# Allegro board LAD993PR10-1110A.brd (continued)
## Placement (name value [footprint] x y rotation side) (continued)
PR1105  97.6K_0402_1%  [R_0402]  64.78 85.13 90 bottom
PR1106  10_0402_1%  [R_0402]  70.88 83.1 90 bottom
PR1107  0_0402_5%  [R0402_0OHM]  69.99 83.1 90 bottom
PR1108  49.9_0402_1%  [R_0402]  69.1 83.1 90 bottom
PR1109  100_0402_1%  [R_0402]  68.46 83.1 90 top
PR1110  27.4K_0402_1%  [R_0402]  65.73 85.03 270 top
PR1111  10.2K_0402_1%  [R_0402]  66.62 84.11 90 top
PR1112  1.91K_0402_1%  [R_0402]  68.21 83.1 90 bottom
PR1113  165K_0402_1%  [R_0402]  76.51 85.33 0 bottom
PR1114  16.9K_0402_1%  [R_0402]  76.72 84.14 270 bottom
PR1115  5.62K_0402_1%  [R_0402]  75.83 84.14 270 bottom
PR1116  110K_0402_1%  [R_0402]  74.94 84.14 270 bottom
PR1117  0_0402_5%  [R0402_0OHM]  67.57 83.1 90 top
PR1118  3.6K_0402_1%  [R_0402]  65.72 87.75 0 top
PR1119  2K_0402_1%  [R_0402]  65.72 88.76 0 bottom
PR1120  0_0402_5%  [R0402_0OHM]  67.32 83.1 90 bottom
PR1121  1.1K_0402_1%  [R_0402]  76.51 88 0 bottom
PR1122  1K_0402_1%  [R_0402]  66.56 86.91 90 bottom
PR1123  48.7K_0402_1%  [R_0402]  76.51 86.22 0 bottom
PR1124  1K_0402_1%  [R_0402]  78.37 87.1 90 bottom
PR1125  2.61K_0402_1%  [R_0402]  129.17 118.1 180 bottom
PR1126  11K_0402_1%  [R_0402]  79.44 86.35 0 bottom
PR1127  2.94K_0402_1%  [R_0402]  64.7 87.81 0 bottom
PR1128  1K_0402_1%  [R_0402]  80.72 91.1 90 bottom
PR1129  2.67K_0402_1%  [R_0402]  80.71 90.16 0 bottom
PR1130  2.61K_0402_1%  [R_0402]  86.88 121.35 270 bottom
PR1131  11K_0402_1%  [R_0402]  63.43 91.43 0 bottom
PR1132  1K_0402_1%  [R_0402]  65.73 90.49 270 top
PR1133  4.42K_0402_1%  [R_0402]  78.55 92.57 0 bottom
PR1134  2K_0402_1%  [R_0402]  76.77 90.67 0 bottom
PR1135  115K_0402_1%  [R_0402]  76.74 92.61 0 bottom
PR1136  432_0402_1%  [R_0402]  66.62 90.49 270 top
PR1137  374_0402_1%  [R_0402]  76.6 95.75 180 bottom
PR1138  11K_0402_1%  [R_0402]  74.81 96.69 90 bottom
PR1139  1K_0402_1%  [R_0402]  76.34 97.6 270 bottom
PR1140  2.61K_0402_1%  [R_0402]  118.88 114.49 270 bottom
PR1141  10.2K_0402_1%  [R_0402]  68.84 95.7 270 bottom
PR1142  1K_0402_1%  [R_0402]  70.62 96.94 90 top
PR1143  90.9K_0402_1%  [R_0402]  67.07 94.78 90 bottom
PR1144  27.4K_0402_1%  [R_0402]  68.84 96.69 90 bottom
PR1145  2K_0402_1%  [R_0402]  70.62 94.78 90 bottom
PR1146  2.43K_0402_1%  [R_0402]  70.61 95.62 0 top
PR1147  4.87K_0402_1%  [R_0402]  69.73 94.78 90 bottom
PR1400  1_0402_5%  [R_0402]  122.56 129.45 270 top
PR1401  0_0402_5%  [R0402_0OHM]  121.45 131.84 270 bottom
PR1402  1_0402_5%  [R_0402]  123.23 131.84 270 bottom
PR1403  10K_0402_1%  [R_0402]  120.98 129.73 270 bottom
PR1404  0_0402_5%  [R0402_0OHM]  122.34 131.84 270 bottom
PR1405  4.7_0603_1%  [R_0603]  126.5 132.26 270 bottom
PR1406  10_1206_5%  [R_1206]  124.79 121.28 0 top
PR1407  0_0402_5%  [R0402_0OHM-NPM]  123.77 120.14 270 bottom
PR1408  0_0402_5%  [R0402_0OHM-NPM]  123.77 115.93 90 bottom
PR1409  100K_0402_1%  [R_0402]  79.21 101.21 180 bottom
PR1410  3.65K_0603_1%  [R_0603]  79.7 102.35 180 bottom
PR1411  2.2_0402_1%  [R_0402]  75.65 102.1 180 bottom
PR1412  100K_0402_1%  [R_0402]  74.74 101.08 0 bottom
PR1413  100K_0402_1%  [R_0402]  75.65 100.07 180 bottom
PR1414  1_0402_5%  [R_0402]  110.88 129.73 270 top
PR1415  0_0402_5%  [R0402_0OHM]  111.01 132.02 270 bottom
PR1416  1_0402_5%  [R_0402]  112.79 132.02 270 bottom
PR1417  0_0402_5%  [R0402_0OHM]  111.9 132.02 270 bottom
PR1418  10K_0402_1%  [R_0402]  110.82 129.73 270 bottom
PR1419  4.7_0603_1%  [R_0603]  116.09 132.18 270 bottom
PR1420  10_1206_5%  [R_1206]  113.99 121.28 0 top
PR1421  0_0402_5%  [R0402_0OHM-NPM]  114.88 120.21 270 bottom
PR1422  0_0402_5%  [R0402_0OHM-NPM]  114.88 115.99 90 bottom
PR1423  100K_0402_1%  [R_0402]  77.23 103.06 270 bottom
PR1424  3.65K_0603_1%  [R_0603]  77.04 104.26 180 bottom
PR1425  2.2_0402_1%  [R_0402]  73.37 102.1 180 bottom
PR1426  100K_0402_1%  [R_0402]  73.37 101.08 180 bottom
PR1427  100K_0402_1%  [R_0402]  73.37 100.07 180 bottom
PR1428  1_0402_5%  [R_0402]  100.9 129.61 270 top
PR1429  0_0402_5%  [R0402_0OHM]  101.23 131.89 270 bottom
PR1430  1_0402_5%  [R_0402]  103.13 131.89 270 bottom
PR1431  0_0402_5%  [R0402_0OHM]  102.17 131.89 270 bottom
PR1432  10K_0402_1%  [R_0402]  100.91 129.61 270 bottom
PR1433  4.7_0603_1%  [R_0603]  106.44 132.13 270 bottom
PR1434  10_1206_5%  [R_1206]  104.09 121.15 0 top
PR1435  0_0402_5%  [R0402_0OHM-NPM]  105.23 119.98 270 bottom
PR1436  0_0402_5%  [R0402_0OHM-NPM]  105.23 115.89 90 bottom
PR1437  100K_0402_1%  [R_0402]  72.45 104.38 0 bottom
PR1438  3.65K_0603_1%  [R_0603]  74.11 106.04 0 bottom
PR1439  2.2_0402_1%  [R_0402]  70.95 102.1 180 bottom
PR1440  100K_0402_1%  [R_0402]  70.95 100.07 180 bottom
PR1441  100K_0402_1%  [R_0402]  70.95 101.08 180 bottom
PR1500  1_0402_5%  [R_0402]  90.69 129.61 270 top
PR1501  0_0402_5%  [R0402_0OHM]  91.07 131.89 270 bottom
PR1502  1_0402_5%  [R_0402]  92.85 131.89 270 bottom
PR1503  0_0402_5%  [R0402_0OHM]  91.96 131.89 270 bottom
PR1504  10K_0402_1%  [R_0402]  90.75 129.61 270 bottom
PR1505  4.7_0603_1%  [R_0603]  96.15 132.13 270 bottom
PR1506  0_0402_5%  [R0402_0OHM-NPM]  91.83 120.08 270 bottom
PR1507  0_0402_5%  [R0402_0OHM-NPM]  91.83 115.86 90 bottom
PR1508  4.7_1206_5%  [R_1206]  93.8 121.15 0 top
PR1509  3.65K_0603_1%  [R_0603]  65.35 102.23 180 bottom
PR1510  100K_0402_1%  [R_0402]  64.86 101.08 180 bottom
PR1511  2.2_0402_1%  [R_0402]  65.87 103.37 180 bottom
PR1512  1_0402_5%  [R_0402]  71.51 106.97 90 bottom
PR1513  0_0402_5%  [R0402_0OHM]  67.37 108.58 0 bottom
PR1514  1_0402_5%  [R_0402]  67.37 110.35 0 bottom
PR1515  0_0402_5%  [R0402_0OHM]  67.37 109.46 0 bottom
PR1516  10K_0402_1%  [R_0402]  70.62 106.97 90 bottom
PR1517  4.7_0603_1%  [R_0603]  67.13 113.66 0 bottom
PR1518  4.7_1206_5%  [R_1206]  76.93 115.79 0 top
PR1519  0_0402_5%  [R0402_0OHM-NPM]  80.07 116.96 0 bottom
PR1520  0_0402_5%  [R0402_0OHM-NPM]  84.29 116.96 180 bottom
PR1521  3.65K_0603_1%  [R_0603]  66.49 106.54 180 bottom
PR1522  100K_0402_1%  [R_0402]  66.61 105.27 0 bottom
PR1523  2.2_0402_1%  [R_0402]  65.87 104.38 180 bottom
PR1524  4.7_1206_5%  [R_1206]  133.3 120.39 0 top
PR1525  100K_0402_1%  [R_0402]  65.87 103.37 180 top
PR1526  100K_0402_1%  [R_0402]  65.87 104.38 180 top
PR1527  1_0603_5%  [R_0603]  135.26 130.42 270 bottom
PR1528  3.65K_0603_1%  [R_0603]  132.79 117.21 180 top
PR1529  0_0402_5%  [R0402_0OHM]  132.55 116.07 180 top
PR1530  0_0402_5%  [R0402_0OHM]  131.84 130.17 270 bottom
PR1531  1_0402_5%  [R_0402]  132.85 130.17 270 top
PR1532  0_0402_5%  [R0402_0OHM]  130.69 127.37 90 bottom
PR1533  1_0402_5%  [R_0402]  130.82 127.83 270 top
PR1600  10K_0402_1%  [R_0402]  177.45 59.4 270 bottom
PR1601  0_0402_5%  [R0402_0OHM]  178.83 58.18 0 top
PR1602  169K_0402_1%  [R_0402]  176.51 58.49 90 bottom
PR1603  0_0402_5%  [R0402_0OHM]  178.78 59.43 270 bottom
PR1606  20.5K_0402_1%  [R_0402]  178.83 55.51 0 top
PR1607  4.32K_0402_1%  [R_0402]  178.83 56.41 0 bottom
PR1608  6.19K_0402_1%  [R_0402]  179.74 56.38 180 top
PR1609  16.5K_0402_1%  [R_0402]  178.82 57.37 0 bottom
PR1610  2.2_0603_5%  [R_0603]  173.5 57.96 90 bottom
PR1611  10_1206_5%  [R_1206]  162.95 60.37 270 top
PR1612  309_0402_1%  [R_0402]  181.11 57.39 270 bottom
PR1613  2.2_0603_5%  [R_0603]  172.73 54.96 180 bottom
PR1614  20_0402_1%  [R_0402]  178.85 53.33 0 top
PR1615  453K_0402_1%  [R_0402]  179.77 53.33 180 bottom
PR1616  2.2_0603_5%  [R_0603]  173.48 51.93 270 bottom
PR1617  100_0402_1%  [R_0402]  179.77 52.44 180 top
PR1618  0_0402_5%  [R0402_0OHM]  179.77 52.45 180 bottom
PR1619  0_0402_5%  [R0402_0OHM]  175.55 51.76 270 bottom
PR1620  0_0402_5%  [R0402_0OHM]  179.59 50.47 180 bottom
PR1621  100K_0402_1%  [R_0402]  176.57 51.78 270 top
PR1622  10_1206_5%  [R_1206]  146.72 58.16 180 top
PR1623  100_0402_1%  [R_0402]  177.66 50.84 90 bottom
PR1624  10K_0402_5%  [R_0402]  175.55 51.73 270 top
PR1700  10K_0402_1%  [R_0402]  200.77 51.58 0 top
PR1701  0_0402_5%  [R_0402]  201.68 50.66 180 top
PR1702  0_0402_5%  [R0402_0OHM]  201.68 52.47 180 top
PR1703  0_0402_5%  [R0402_0OHM]  200.79 49.72 0 top
PR1706  20.5K_0402_1%  [R_0402]  204.35 48.94 270 bottom
PR1707  4.32K_0402_1%  [R_0402]  203.46 48.86 270 top
PR1708  6.19K_0402_1%  [R_0402]  203.46 48.02 90 bottom
PR1709  16.5K_0402_1%  [R_0402]  202.57 48.86 270 top
PR1710  10_1206_5%  [R_1206]  193.39 66.84 90 top
PR1711  2.2_0603_5%  [R_0603]  202.32 56.01 90 top
PR1712  309_0402_1%  [R_0402]  201.69 47.95 90 top
PR1713  2.2_0603_5%  [R_0603]  206.59 55.98 90 top
PR1714  20_0402_1%  [R_0402]  208.42 48.94 270 top
PR1715  412K_0402_1%  [R_0402]  207.53 48.02 90 top
PR1716  100_0402_1%  [R_0402]  210.19 48.25 180 top
PR1717  0_0402_5%  [R0402_0OHM]  210.19 49.16 180 top
PR1719  82.5K_0402_1%  [R_0402]  208.42 53.86 0 top
PR1720  0_0402_5%  [R0402_0OHM]  210.19 50.05 90 top
PR1721  100_0402_1%  [R_0402]  209.31 51.88 270 top
PR1800  100K_0402_1%  [R_0402]  150.78 20.6 180 bottom
PR1801  0_0402_5%  [R0402_0OHM]  147.15 16.31 180 bottom
PR1803  21.5K_0402_1%  [R_0402]  146.14 26.74 0 bottom
PR1804  10K_0402_1%  [R_0402]  148.16 26.75 270 bottom
PR1805  0_0603_1%  [R_0603]  144.1 26.88 180 top
PT1400  PAD~D  [TPC12]  121.04 125.09 90 bottom
PT1401  PAD~D  [TPC12]  110.88 125.09 90 bottom
PT1402  PAD~D  [TPC12]  100.97 125.09 90 bottom
PT1500  PAD~D  [TPC12]  89.67 125.09 90 bottom
PT1501  PAD~D  [TPC12]  74.86 107.53 180 bottom
PT1503  PAD~D  [TPC12]  130.72 124.41 180 bottom
PU300  BQ24780SRUYR_QFN28_4X4  [BQ24780RUYR_WQFN28_4X4-S]  27.82 36.14 0 bottom
PU400  -  [TPS51285BRUKR_QFN20_3X3]  53.82 22.36 180 bottom
PU500  SY8210AQVC_QFN19_4X3  [SY8210AQVC_QFN19_4X3-S]  99.35 12.91 0 bottom
PU600  -  [SY8286RAC_QFN20_3X3]  249.55 17.16 270 bottom
PU700  -  [SY8286RAC_QFN20_3X3]  68.4 69.04 270 top
PU800  -  [SY8286RAC_QFN20_3X3]  222.26 45.2 270 bottom
PU900  APW8828QBI-TRG_TDFN10_3X3  [TPS51212DSCR_SON10_3X3-S]  141.81 111.56 180 bottom
PU1000  -  [SY8286RAC_QFN20_3X3]  206.12 119.95 270 bottom
PU1100  ISL95829AHRTZ-T_TQFN48_6X6  [ISL95855HRTZTS27_TQFN48_6X6-S]  68.72 87.37 0 bottom
PU1400  -  [SIC632CDT1GE3_POWERPAK31_5X5]  123.16 129.18 270 bottom
PU1401  -  [SIC632CDT1GE3_POWERPAK31_5X5]  113 129.18 270 bottom
PU1402  -  [SIC632CDT1GE3_POWERPAK31_5X5]  103.1 129.05 270 bottom
PU1500  -  [SIC632CDT1GE3_POWERPAK31_5X5]  92.81 129.05 270 bottom
PU1501  -  [SIC632CDT1GE3_POWERPAK31_5X5]  70.11 110.32 0 bottom
PU1503  SIC531CDT1GE3_POWERPAK22_4X3  [SIC531CDT1GE3_POWERPAK22_4X3-S]  132.85 127.24 270 bottom
PU1600  -  [RT8816AGQW_WQFN20_3X3]  174.84 56.48 0 bottom
PU1700  -  [RT8816AGQW_WQFN20_3X3]  203.64 53.76 270 top
PU1800  -  [RT9059GSP_SO8]  147.5 18.98 180 bottom
Q12  L2N7002LT1G_SOT23-3  [2N7002K_SOT23-3]  58.94 31.11 180 top
Q13  L2N7002LT1G_SOT23-3  [2N7002K_SOT23-3]  244.36 32.02 180 top
QA1  -  [L2N7002WT1G_SC-70-3]  264.55 27.36 0 bottom
QA2  SI3457BDV-T1-E3_TSOP6~D  [SI3457BDV-T1-E3_TSOP6]  261.06 30.58 270 bottom
QE3  -  [L2N7002WT1G_SC-70-3]  213.44 32.5 90 top
QE4  -  [DMG2301U-7_SOT23-3]  210.83 34.31 180 top
QE5  -  [L2N7002WT1G_SC-70-3]  118.56 15.71 270 top
QE13  -  [L2N7002WT1G_SC-70-3]  133.1 15.9 0 top
QE19  2N7002EDW 2N SOT-363-6  [DMN65D8LDW-7_SOT363-6]  148.78 16.35 90 bottom
QE20  2N7002EDW 2N SOT-363-6  [DMN65D8LDW-7_SOT363-6]  253.12 28.95 180 top
QE21  2N7002EDW 2N SOT-363-6  [DMN65D8LDW-7_SOT363-6]  256.55 27.17 90 top
QE23  2N7002EDW 2N SOT-363-6  [DMN65D8LDW-7_SOT363-6]  247.15 27.04 0 top
QE24  2N7002EDW 2N SOT-363-6  [DMN65D8LDW-7_SOT363-6]  285.62 58.98 0 bottom
QH4  2N7002EDW 2N SOT-363-6  [DMN65D8LDW-7_SOT363-6]  152.47 21.37 90 top
QH5  2N7002EDW 2N SOT-363-6  [DMN65D8LDW-7_SOT363-6]  151.92 23.81 180 bottom
QT1  MMBT3904WH_SOT323-3  [MMST3904-7-F_SOT323-3]  150.18 75.56 90 top
QT2  2N7002EDW 2N SOT-363-6  [DMN65D8LDW-7_SOT363-6]  52.4 47.35 90 bottom
QT3  MMBT3904WH_SOT323-3  [MMST3904-7-F_SOT323-3]  215.43 14.83 270 bottom
QV1  DMN63D8LDW-7 2N SOT363-6  [DMN65D8LDW-7_SOT363-6]  149.17 73.46 270 bottom
QV2  -  [L2N7002WT1G_SC-70-3]  66.81 23.93 180 top
QV3  BSS138W 1N SOT-323-3  [2N7002W-T-R7_SOT323-3]  147.71 77.85 0 top
QV10  BSS138W 1N SOT-323-3  [2N7002W-T-R7_SOT323-3]  177.26 63.08 0 top
QV11  SI3457BDV-T1-E3_TSOP6~D  [SI3457BDV-T1-E3_TSOP6]  62.38 21 0 top
QV20  BSS138W 1N SOT-323-3  [2N7002W-T-R7_SOT323-3]  191.02 119.15 0 bottom
QV21  BSS138W 1N SOT-323-3  [2N7002W-T-R7_SOT323-3]  194.74 74.41 270 bottom
QV88  DMN63D8LDW-7 2N SOT363-6  [DMN65D8LDW-7_SOT363-6]  151.09 76.65 180 bottom
QV89  -  [L2N7002WT1G_SC-70-3]  172.73 69.71 0 top
QV90  DMN61D9UDW-7 2N SOT363-6  [DMN65D8LDW-7_SOT363-6]  190.96 61.47 270 top
QV92  DMN63D8LDW-7 2N SOT363-6  [DMN65D8LDW-7_SOT363-6]  207.37 60.1 90 top
QV93  S TR METR3904W-G NPN SOT323-3  [MMST3904-7-F_SOT323-3]  228.8 17.55 90 bottom
QZ6  DMN63D8LDW-7 2N SOT363-6  [DMN65D8LDW-7_SOT363-6]  204.35 70.6 0 top
QZ7  DMN63D8LDW-7 2N SOT363-6  [DMN65D8LDW-7_SOT363-6]  157.5 77.55 90 top
QZ8  DMN63D8LDW-7 2N SOT363-6  [DMN65D8LDW-7_SOT363-6]  150.09 107.03 270 top
QZ9  -  [DMG2301U-7_SOT23-3]  210.98 47.79 270 bottom
QZ10  DMN63D8LDW-7 2N SOT363-6  [DMN65D8LDW-7_SOT363-6]  155.49 79.97 0 top
QZ11  -  [L2N7002WT1G_SC-70-3]  150.62 80.06 0 top
QZ12  DMN63D8LDW-7 2N SOT363-6  [DMN65D8LDW-7_SOT363-6]  153.81 80.06 180 top
QZ13  DMN63D8LDW-7 2N SOT363-6  [DMN65D8LDW-7_SOT363-6]  30.47 39.26 0 top
R1  1M_0402_5%  [R_0402]  30.26 35.68 90 top
R2  4.7K_0805_5%  [R_0805]  28.74 41.07 270 top
R3  1M_0402_5%  [R_0402]  28.88 42.1 0 top
R4  1M_0402_5%  [R_0402]  30.63 42.1 0 top
R5  1M_0402_5%  [R_0402]  32.01 37.71 180 top
RA1  0_0402_5%  [R0402_0OHM]  286.2 30.23 270 bottom
RA2  10K_0402_5%  [R_0402]  289.32 39.16 90 top
RA3  0_0603_5%  [R0603_0OHM]  288.49 30.22 90 top
RA5  0_0402_5%  [R0402_0OHM]  274.13 18.41 0 top
RA7  0_0805_5%  [R0805_0OHM]  273.38 32.78 270 bottom
RA8  0_0603_5%  [R0603_0OHM]  290.73 22.99 45 top
RA9  0_0402_5%  [R0402_0OHM]  279.01 21.79 135 bottom
RA10  0_0805_5%  [R0805_0OHM]  275.09 32.78 270 bottom
RA11  100K_0402_5%  [R_0402]  287.87 21.33 180 top
RA12  0_0402_5%  [R0402_0OHM]  291.47 14.29 270 bottom
RA13  0_0402_5%  [R0402_0OHM]  292.16 22.22 0 top
RA14  0_0402_5%  [R0402_0OHM]  284.19 23.8 180 bottom
RA15  0_0402_5%  [R0402_0OHM]  294.98 11.8 180 top
RA16  0_0805_5%  [R0805_0OHM]  279.05 17.68 270 bottom
RA17  0_0402_5%  [R_0402]  281.44 18.74 270 top
RA18  0_0402_5%  [R0402_0OHM]  282.33 18.74 270 top
RA19  0_0402_5%  [R0402_0OHM]  279.41 20.13 270 top
RA22  200K_0402_5%  [R_0402]  278.46 19.18 270 top
RA23  100K_0402_5%  [R_0402]  275.6 30.6 270 top
RA24  100K_0402_5%  [R_0402]  275.9 18.41 0 top
RA27  0_0402_5%  [R0402_0OHM]  272.22 27.23 0 top
RA28  22_0402_5%  [R_0402]  272.22 26.34 0 top
RA29  0_0402_5%  [R0402_0OHM]  274.63 25.9 0 bottom
RA30  1K_0402_5%  [R_0402]  279.61 15.66 90 top
RA31  0_0402_5%  [R0402_0OHM]  276.36 23.92 0 bottom
RA32  33_0402_5%  [R_0402]  274.51 23.74 0 top
RA33  10K_0402_5%  [R_0402]  280.5 16.58 270 top
RA35  4.7_0402_5%  [R_0402]  273.62 23.99 0 bottom
RA36  10_0201_5%  [R_0201]  270.46 23.83 90 top
RA37  10_0201_5%  [R_0201]  273.25 23.95 90 top
RA42  2.2K_0402_5%  [R_0402]  287.49 20.06 180 bottom
RA43  2.2K_0402_5%  [R_0402]  288.99 20.06 0 bottom
RA44  10_0402_1%  [R_0402]  296.48 13.2 0 top
RA46  4.7K_0402_5%  [R_0402]  296.48 12.31 0 top
RA48  1K_0402_5%  [R_0402]  296.48 14.09 0 top
RA49  10_0402_1%  [R_0402]  292.57 15.36 180 top
RA51  1K_0402_5%  [R_0402]  292.57 14.47 180 top
RA53  4.7K_0402_5%  [R_0402]  292.57 16.25 180 top
RA54  10K_0402_5%  [R_0402]  292.57 18.02 180 top
RA55  10K_0402_5%  [R_0402]  296.48 15.99 0 top
RA56  0_0402_5%  [R0402_0OHM]  291.6 15.79 90 bottom
RA57  10_0402_5%  [R_0402]  257.95 16.83 270 bottom
RA58  10_0402_5%  [R_0402]  269.12 16.68 90 bottom
RA60  0_0402_5%  [R_0402]  269.2 22.34 180 bottom
RA61  0_0402_5%  [R_0402]  269.2 23.49 180 bottom
RA62  10K_0402_5%  [R_0402]  268.28 21.45 0 bottom
RA63  10K_0402_5%  [R_0402]  266.33 23.94 270 bottom
RA64  10K_0402_5%  [R_0402]  268.28 24.37 0 bottom
RA65  45.3K_0402_1%  [R_0402]  261.88 23.94 270 bottom
RA66  0_0402_5%  [R_0402]  265.44 23.03 90 bottom
RA67  0_0402_5%  [R_0402]  262.77 23.03 90 bottom
RA70  100K_0402_5%  [R_0402]  276.49 26.96 90 bottom
RA71  1K_0402_1%  [R_0402]  284.62 17.44 90 top
RA72  1.2K_0201_1%  [R_0201]  283.73 18.35 270 top
RA73  665_0402_1%  [R_0402]  257.92 23.64 270 bottom
RA74  100K_0402_5%  [R_0402]  257.85 20.89 0 bottom
RA75  0_0805_5%  [R_0805]  270.52 20.4 270 bottom
RA76  0_0805_5%  [R0805_0OHM]  268.61 20.4 270 bottom
RA79  100K_0402_5%  [R_0402]  261.68 27.04 0 bottom
RA80  1M_0402_5%  [R_0402]  259.14 25.77 0 bottom
RC11  1K_0402_5%  [R_0402]  154.51 16.97 270 bottom
RD7  10K_0402_5%  [R_0402]  218.27 27.8 180 bottom
RD8  10K_0402_5%  [R_0402]  217.56 23.61 0 bottom
RD9  0_0402_5%  [R_0402]  218.15 21.2 180 bottom
RD10  10K_0402_5%  [R_0402]  205.11 19.88 270 bottom
RD31  0_0402_5%  [R0402_0OHM]  96.96 17.49 270 bottom
RD35  470_0402_1%  [R_0402]  97.85 17.49 270 bottom
RD58  0_0402_5%  [R0402_0OHM]  204.23 19.88 270 bottom
RD59  0_0402_5%  [R0402_0OHM]  217.43 26.79 0 bottom
RD62  0_0402_5%  [R_0402]  194.07 17.47 270 top
RE1  100K_0402_5%  [R_0402]  214.13 34.33 90 top
RE2  240_0402_1%  [R_0402]  209.86 36.19 0 top
RE3  47K_0402_5%  [R_0402]  120.65 16.55 270 top
RE4  100K_0402_1%  [R_0402]  119.76 16.55 270 top
RE7  2.4K_0402_5%  [R_0402]  149.81 15.08 270 bottom
RE9  2.4K_0402_5%  [R_0402]  149.87 19.69 0 bottom
RE10  10_0402_5%  [R_0402]  228.99 12.11 90 top
RE12  0_0603_5%  [R0603_0OHM]  240.4 20.37 180 top
RE13  27K_0402_1%~D  [R_0402]  230.58 28.74 90 bottom
RE14  100K_0402_1%  [R_0402]  229.69 28.74 90 bottom
RE15  0_0603_5%  [R0603_0OHM]  224.93 16.14 0 bottom
RE16  0_0603_5%  [R0603_0OHM]  221.94 34.66 0 bottom
RE17  43_0402_1%  [R_0402]  238.44 29.45 0 top
RE20  1K_0402_5%  [R_0402]  225.18 27.24 270 bottom
RE21  1K_0402_5%  [R_0402]  238.44 25.52 0 top
RE22  100K_0402_5%  [R_0402]  223.78 28.74 90 bottom
RE23  10K_0402_5%  [R_0402]  232.99 20.59 180 bottom
RE24  4.7K_0402_5%  [R_0402]  235.39 23.1 0 bottom
RE25  100K_0402_5%  [R_0402]  241.77 25.92 180 top
RE27  100K_0402_5%  [R_0402]  235.39 26.66 0 bottom
RE28  10K_0402_5%  [R_0402]  226.07 29.66 270 bottom
RE29  100K_0402_5%  [R_0402]  216.6 27.04 180 top
RE30  100K_0402_5%  [R_0402]  236.23 19.17 180 bottom
RE31  100K_0402_5%  [R_0402]  222.51 32.07 270 bottom
RE33  100K_0402_5%  [R_0402]  232.6 24.76 0 bottom
RE34  10K_0402_1%  [R_0402]  222.67 21.25 0 bottom
RE35  10K_0402_1%  [R_0402]  223.58 22.14 180 bottom
RE36  300_0402_5%  [R_0402]  232.61 27.5 270 bottom
RE38  100K_0402_5%  [R_0402]  232.6 23.87 0 bottom
RE39  100K_0402_5%  [R_0402]  217.76 29.33 180 top
RE40  15_0402_1%  [R_0402]  216.21 17.08 0 top
RE41  15_0402_1%  [R_0402]  216.21 19.8 0 top
RE42  15_0402_1%  [R_0402]  216.21 18.86 0 top
RE43  4.7K_0402_5%  [R_0402]  223.07 27.17 0 bottom
RE44  4.7K_0402_5%  [R_0402]  223.07 26.28 0 bottom
RE45  2.2K_0402_5%  [R_0402]  223.07 25.26 0 bottom
RE46  2.2K_0402_5%  [R_0402]  223.07 24.25 0 bottom
RE47  10K_0402_5%  [R_0402]  221.93 29.02 0 bottom
RE52  100K_0402_5%  [R_0402]  223.4 31.16 90 bottom
RE53  100K_0402_5%  [R_0402]  222.5 13.93 270 top
RE55  4.7K_0402_5%  [R_0402]  235.39 23.99 0 bottom
RE57  0_0402_5%  [R0402_0OHM]  238.44 27.55 0 top
RE58  0_0402_5%  [R0402_0OHM]  225.18 29.66 270 bottom
RE59  0_0402_5%  [R0402_0OHM]  216.21 20.69 0 top
RE60  49.9_0402_1%  [R_0402]  245.45 34.28 180 bottom
RE61  0_0402_5%  [R0402_0OHM]  221.61 13.93 270 top
RE62  0_0402_5%  [R0402_0OHM]  226.1 12.74 0 bottom
RE63  10K_0402_5%  [R_0402]  254.01 31.41 90 bottom
RE64  10K_0402_5%  [R_0402]  255.91 31.41 90 bottom
RE65  100K_0402_5%  [R_0402]  255.03 31.41 90 bottom
RE66  0_0402_5%  [R_0402]  223.61 34.53 180 top
RE67  0_0603_5%  [R0603_0OHM]  227.54 25.94 90 bottom
RE68  0_0402_5%  [R0402_0OHM]  240.85 26.81 0 top
RE71  15_0402_1%  [R_0402]  171.13 10.79 0 bottom
RE73  0_0402_5%  [R0402_0OHM]  233.56 25.82 90 bottom
RE81  100K_0402_5%  [R_0402]  52.08 31.94 270 top
RE82  10K_0402_5%  [R_0402]  55.76 29.59 180 top
RE83  100K_0402_5%  [R_0402]  51.19 31.94 270 top
RE84  10K_0402_5%  [R_0402]  243.57 36.95 0 top
RE87  100K_0402_5%  [R_0402]  134.82 14.91 270 top
RE93  0_0603_5%  [R0603_0OHM]  134.97 17.16 180 top
RE100  10K_0402_5%  [R_0402]  56.39 31.08 90 top
RE101  10K_0402_5%  [R_0402]  243.57 34.41 0 top
RE104  0_0603_5%  [R0603_0OHM]  55.25 30.55 90 top
RE105  0_0603_5%  [R0603_0OHM]  243.07 35.68 0 top
RE106  0_0402_5%  [R0402_0OHM]  220.79 34.53 0 top
RE108  10K_0402_5%  [R_0402]  216.21 17.97 0 top
RE109  0_0402_5%  [R0402_0OHM]  250.07 32.32 270 bottom
RE110  0_0402_5%  [R0402_0OHM]  251.09 32.32 270 bottom
RE111  0_0402_5%  [R0402_0OHM]  252.1 32.32 270 bottom
RE112  0_0402_5%  [R0402_0OHM]  253.12 32.32 270 bottom
RE113  100K_0402_5%  [R_0402]  230.51 34.46 90 top
RE114  100K_0402_5%  [R_0402]  239.35 28.44 180 top
RE116  0_0402_5%  [R0402_0OHM]  236.92 29.58 0 bottom
RE118  10K_0402_5%  [R_0402]  256.75 33.39 180 bottom
RE119  100K_0402_5%  [R_0402]  238.39 19.04 90 bottom
RE120  100K_0402_5%  [R_0402]  216.42 32.96 270 top
RE121  10K_0402_5%  [R_0402]  57.97 27.21 0 top
RE122  10K_0402_5%  [R_0402]  243.77 28.06 0 top
RE123  100K_0402_5%  [R_0402]  141.83 17.26 270 bottom
RE124  100K_0402_1%  [R_0402]  228.23 31.26 180 bottom
RE125  10K_0402_1%  [R_0402]  226.32 31.23 90 bottom
RE126  15_0402_1%  [R_0402]  171.26 8.37 0 bottom
RE127  15_0402_1%  [R_0402]  185.23 11.14 180 bottom
RE128  15_0402_1%  [R_0402]  171.26 7.36 0 bottom
RE129  15_0402_1%  [R_0402]  184.39 9.34 90 bottom
RH1  0_0402_5%  [R_0402]  168.79 14.54 270 bottom
RH9  0_0402_5%  [R0402_0OHM]  179.79 26.79 180 top
RH10  10K_0402_5%  [R_0402]  159.33 17.67 90 top
RH11  0_0402_5%  [R0402_0OHM]  173.8 14.21 0 bottom
RH13  100K_0402_5%  [R_0402]  178.52 25.9 180 top
RH14  5.1K_0402_1%  [R_0402]  153.86 25.52 0 top
RH15  5.1K_0402_1%  [R_0402]  153.86 24.63 0 top
RH16  22_0402_5%  [R_0402]  184.27 25.21 0 top
RH17  1K_0402_5%  [R_0402]  171.08 16.32 270 bottom
RH18  1K_0402_5%  [R_0402]  186.83 14.52 90 top
RH20  0_0402_5%  [R_0402]  160.81 35.72 0 top
RH21  1K_0402_5%  [R_0402]  149.5 20.36 90 top
RH22  1K_0402_5%  [R_0402]  154.52 22.72 180 top
RH23  1K_0402_5%  [R_0402]  158.71 24.29 180 top
RH24  24.9_0402_1%  [R_0402]  126.68 68.57 0 bottom
RH25  1K_0402_5%  [R_0402]  158.71 25.64 180 top
RH26  1K_0402_5%  [R_0402]  148.52 22.72 0 top
RH27  1K_0402_5%  [R_0402]  154.51 21.19 180 top
RH28  0_0402_5%  [R0402_0OHM]  105.78 105.23 180 bottom
RH29  100_0402_1%  [R_0402]  106.7 105.23 0 bottom
RH30  24.9_0402_1%  [R_0402]  127.14 99.99 90 top
RH31  0_0402_5%  [R0402_0OHM]  117.52 103.22 90 bottom
RH32  0_0402_5%  [R0402_0OHM]  105.78 104.27 180 bottom
RH33  100_0402_1%  [R_0402]  106.7 104.27 0 bottom
RH34  0_0402_5%  [R0402_0OHM]  114.26 82.16 270 top
RH38  0_0402_5%  [R0402_0OHM]  84.39 92.19 0 bottom
RH41  100_0402_1%  [R_0402]  116.63 103.22 90 bottom
RH45  2_0402_1%  [R_0402]  68.16 43.78 0 top
RH46  2_0402_1%  [R_0402]  111.39 20.51 270 top
RH47  0_0402_5%  [R0402_0OHM]  187.84 14.52 90 top
RH56  51_0402_5%  [R_0402]  84.9 95.88 0 top
RH57  49.9_0402_1%  [R_0402]  84.39 88.64 0 bottom
RH58  49.9_0402_1%  [R_0402]  84.39 90.41 0 bottom
RH59  49.9_0402_1%  [R_0402]  85.3 89.53 180 bottom
RH60  51_0402_5%  [R_0402]  82.1 95.49 0 bottom
RH61  51_0402_5%  [R_0402]  84.39 91.3 0 bottom
RH62  499_0402_1%  [R_0402]  150.81 27.17 0 bottom
RH63  499_0402_1%  [R_0402]  158 20.23 90 top
RH64  4.7K_0402_5%  [R_0402]  159.65 24.25 0 top
RH65  150K_0402_5%  [R_0402]  165.09 28.94 270 top
RH66  4.7K_0402_5%  [R_0402]  157.11 20.23 90 top
RH67  1M_0402_5%  [R_0402]  169.68 18.86 270 top
RH68  10K_0402_5%  [R_0402]  154.74 33.31 180 top
RH69  10K_0402_5%  [R_0402]  154.87 30.13 180 bottom
RH70  10M_0402_5%  [R_0402]  175.47 19.04 180 bottom
RH71  2.7K_0402_1%  [R_0402]  179.25 40.45 90 top
RH72  1M_0402_5%  [R_0402]  182 45.02 270 bottom
RH74  4.7K_0402_5%  [R_0402]  162.58 15.57 180 bottom
RH77  100K_0402_5%  [R_0402]  169.67 13.52 0 bottom
RH79  10K_0402_5%  [R_0402]  154.52 37.33 180 bottom
RH80  10K_0402_5%  [R_0402]  151.9 31.47 0 top
RH81  8.2K_0402_5%  [R_0402]  170.19 16.14 270 bottom
RH82  4.7K_0402_5%  [R_0402]  165.49 17.95 90 top
RH83  20K_0402_5%  [R_0402]  177.17 18.84 90 top
RH84  20K_0402_5%  [R_0402]  175.4 18.84 90 top
RH85  8.2K_0402_5%  [R_0402]  168.79 18.86 270 top
RH86  10K_0402_5%  [R_0402]  153.73 30.6 0 top
RH87  10K_0402_5%  [R_0402]  180.68 24.88 180 top
RH88  47K_0402_5%  [R_0402]  178.95 18.33 90 top
RH89  0_0402_5%  [R_0402]  154.74 35.21 180 top
RH90  10K_0402_5%  [R_0402]  171.46 18.86 270 bottom
RH91  10K_0402_5%  [R_0402]  153.98 27.93 0 bottom
RH92  4.7K_0402_5%  [R_0402]  164.6 18.46 90 top
RH93  220K_0402_5%  [R_0402]  80.49 81.83 0 bottom
RH94  10K_0402_5%  [R_0402]  187.78 25.07 180 top
RH95  51_0402_5%  [R_0402]  190.38 35.88 270 bottom
RH96  0_0402_5%  [R0402_0OHM]  182.97 19.04 180 bottom
RH97  51_0402_5%  [R_0402]  181.85 34.23 270 top
RH98  51_0402_5%  [R_0402]  183.65 31.56 270 top
RH100  51_0402_5%  [R_0402]  180.96 34.23 270 top
RH101  0_0402_5%  [R0402_0OHM]  161.67 14.63 0 bottom
RH102  0_0402_5%  [R_0402]  187.78 26.86 270 top
RH103  0_0402_5%  [R0402_0OHM]  192.08 23.78 180 top
RH104  22_0402_1%  [R_0402]  163.2 18.86 270 bottom
RH105  0_0402_5%  [R0402_0OHM]  191.16 24.67 0 top
RH106  0_0402_5%  [R0402_0OHM]  192.08 25.56 180 top
RH107  0_0402_5%  [R_0402]  116.37 81.24 0 top
RH108  100_0402_1%  [R_0402]  171 45.88 180 bottom
RH109  113_0402_1%  [R_0402]  179.08 29.86 0 top
RH110  10K_0402_5%  [R_0402]  154.74 32.42 180 top
RH111  10K_0402_5%  [R_0402]  180.68 23.99 180 top
RH112  1K_0402_5%  [R_0402]  175.21 32.46 90 top
RH113  1K_0402_5%  [R_0402]  182.13 34.97 90 bottom
RH114  0_0402_5%  [R0402_0OHM]  173.8 13.33 0 bottom
RH115  0_0402_5%  [R0402_0OHM]  84.9 94.1 0 top
RH118  0_0402_5%  [R0402_0OHM]  84.9 96.76 0 top
RH119  2.2K_0402_5%  [R_0402]  153.86 26.66 0 top
RH120  2.2K_0402_5%  [R_0402]  153.98 26.15 0 bottom
RH121  0_0603_5%  [R0603_0OHM]  171.84 12.25 90 bottom
RH122  0_0603_5%  [R0603_0OHM]  184.92 39.8 270 bottom
RH123  0_0603_5%  [R0603_0OHM]  180.35 28.82 180 top
RH124  0_0603_5%  [R0603_0OHM]  160.22 45.84 180 top
RH125  8.2K_0402_5%  [R_0402]  173.69 14.19 180 top
RH126  10K_0402_5%  [R_0402]  170.05 22.41 0 top
RH127  10K_0402_5%  [R_0402]  163.25 27.97 180 top
RH128  10K_0402_5%  [R_0402]  170.57 18.86 270 bottom
RH129  10K_0402_5%  [R_0402]  154.65 29.71 180 top
RH130  4.7K_0402_5%  [R_0402]  164.19 28.94 270 top
RH131  10K_0402_5%  [R_0402]  154.65 31.49 180 top
RH132  10K_0402_5%  [R_0402]  154.87 32.74 180 bottom
RH134  10K_0402_5%  [R_0402]  154.87 33.63 180 bottom
RH135  10K_0402_5%  [R_0402]  154.74 34.2 180 top
RH137  0_0603_5%  [R0603_0OHM]  166.62 15.64 0 top
RH138  13_0402_5%  [R_0402]  185.68 34.97 90 bottom
RH141  2.2K_0402_5%  [R_0402]  177.86 23.74 0 top
RH142  2.2K_0402_5%  [R_0402]  177.86 22.85 0 top
RH143  330K_0402_5%  [R_0402]  176.29 19.75 270 top
RH144  49.9_0402_1%  [R_0402]  84.9 94.99 0 top
RH145  20_0402_5%  [R_0402]  133.89 95.32 0 top
RH146  30_0402_5%  [R_0402]  188.35 35.88 270 bottom
RH147  30_0402_5%  [R_0402]  189.24 35.88 270 bottom
RH148  121_0402_1%  [R_0402]  124.65 68.57 0 bottom
RH149  75_0402_1%  [R_0402]  121.22 68.95 0 bottom
RH150  100_0402_1%  [R_0402]  123.33 68.62 90 bottom
RH151  100_0402_5%  [R_0402]  85.91 90.29 0 top
RH152  56.2_0402_1%  [R_0402]  84.97 90.21 90 top
RH153  220_0402_5%  [R_0402]  85.91 91.3 0 top
RH154  60.4_0402_1%  [R_0402]  130.74 76.41 90 top
RH155  20_0402_5%  [R_0402]  81.21 98.29 0 bottom
RH156  51_0402_5%  [R_0402]  82.1 93.46 0 bottom
RH158  499_0402_1%  [R_0402]  84.39 94.61 0 bottom
RH159  49.9K_0402_1%  [R_0402]  153.73 27.93 0 top
RH160  49.9K_0402_1%  [R_0402]  153.98 27.04 0 bottom
RH163  1K_0402_5%  [R_0402]  123.16 95.52 180 top
RH164  1K_0402_5%  [R_0402]  131.67 77.32 270 top
RH165  1K_0402_5%  [R_0402]  82.1 94.61 0 bottom
RH166  49.9_0402_1%  [R_0402]  84.39 93.34 0 bottom
RH167  30_0402_5%  [R_0402]  134.81 93.54 180 top
RH168  22_0402_5%  [R_0402]  170.57 18.86 270 top
RH179  10K_0402_5%  [R_0402]  167.01 18.86 270 top
RH180  100K_0402_5%  [R_0402]  189.39 23.78 0 top
RH181  10K_0402_5%  [R_0402]  172.09 16.32 270 bottom
RH183  1K_0402_5%  [R_0402]  89.16 90.87 270 top
RH184  1K_0402_5%  [R_0402]  88.27 90.87 270 top
RH185  1K_0402_5%  [R_0402]  85.3 85.91 180 bottom
RH186  1K_0402_5%  [R_0402]  85.3 84.95 180 bottom
RH187  1K_0402_5%  [R_0402]  85.3 86.86 180 bottom
RH188  1K_0402_5%  [R_0402]  85.3 87.75 180 bottom
RH189  30_0402_5%  [R_0402]  184.16 34.97 90 bottom
RH190  0_0402_5%  [R0402_0OHM]  81.21 99.43 0 bottom
RH191  620_0402_5%  [R_0402]  183.14 34.97 90 bottom
RH192  30_0402_5%  [R_0402]  134.81 94.43 180 top
RH193  8.2K_0402_5%  [R_0402]  182.05 20.06 0 bottom
RH196  0_0402_5%  [R_0402]  167.52 28.9 270 top
RH197  100_0402_1%  [R_0402]  107.62 106.3 180 bottom
RH198  0_0402_5%  [R0402_0OHM]  105.78 106.3 180 bottom
RH201  100_0402_1%  [R_0402]  119.43 103.22 90 bottom
RH202  0_0402_5%  [R0402_0OHM]  118.41 103.22 90 bottom
RH203  100_0402_1%  [R_0402]  107.62 102.81 180 bottom
RH204  0_0402_5%  [R0402_0OHM]  105.78 102.81 180 bottom
RH206  1K_0402_1%  [R_0402]  70.02 43.73 270 top
RH207  1K_0402_1%  [R_0402]  114.31 20.51 270 top
RH209  1K_0402_1%  [R_0402]  69.08 42.77 180 top
RH210  1K_0402_1%  [R_0402]  112.31 19.58 90 top
RH211  24.9_0402_1%  [R_0402]  70.02 44.72 90 top
RH212  24.9_0402_1%  [R_0402]  110.32 18.02 180 top
RH492  0_0402_5%  [R0402_0OHM]  184.54 30.65 90 top
RH493  0_0603_5%  [R0603_0OHM]  152.14 22.7 180 bottom
RH494  10K_0402_5%  [R_0402]  153.73 28.82 0 top
RH495  10K_0402_5%  [R_0402]  155.89 29.07 0 top
RH496  51_0402_5%  [R_0402]  83.07 91.48 90 bottom
RH497  51_0402_5%  [R_0402]  84.9 93.21 0 top
RH499  0_0402_5%  [R_0402]  190.31 22.9 180 top
RH500  10K_0402_5%  [R_0402]  167.9 18.86 270 top
RH502  0_0402_5%  [R0402_0OHM]  253.81 24.76 0 top
RH503  0_0402_5%  [R0402_0OHM]  180.35 18.33 90 top
RH504  100K_0402_5%  [R_0402]  250.58 27.17 90 top
RH505  100K_0402_5%  [R_0402]  249.56 27.17 90 top
RH506  100K_0402_5%  [R_0402]  284.11 58.36 270 bottom
RH507  22_0402_1%  [R_0402]  162.32 18.99 270 bottom
RH508  22_0402_1%  [R_0402]  164.09 18.86 270 bottom
RH509  22_0402_1%  [R_0402]  164.98 18.86 270 bottom
RH510  22_0402_1%  [R_0402]  165.87 18.86 270 bottom
RH513  0_0402_5%  [R0402_0OHM]  121.5 83.3 180 top
RH514  0_0402_5%  [R0402_0OHM]  121.5 84.19 180 top
RH515  100_0402_1%  [R_0402]  123.12 83.81 0 top
RH516  100_0402_1%  [R_0402]  123.12 82.92 0 top
RH517  100K_0402_5%  [R_0402]  176.74 61.37 0 top
RI9  100K_0402_5%  [R_0402]  277.94 34.66 0 top
RI10  100K_0402_5%  [R_0402]  277.94 35.68 0 top
RI30  100K_0402_5%  [R_0402]  277.89 37.71 0 top
RI37  0_0402_5%  [R0402_0OHM]  288.05 31.49 0 bottom
RI38  0_0402_5%  [R0402_0OHM]  288.05 32.5 0 bottom
RI39  0_0402_5%  [R0402_0OHM]  288.02 33.65 0 bottom
RI40  0_0402_5%  [R0402_0OHM]  288.02 34.66 0 bottom
RI41  0_0402_5%  [R0402_0OHM]  288.81 50.66 0 bottom
RI42  0_0402_5%  [R0402_0OHM]  288.81 51.68 0 bottom
RI43  0_0402_5%  [R0402_0OHM]  288.81 52.7 0 bottom
RI44  0_0402_5%  [R0402_0OHM]  288.81 53.71 0 bottom
RI45  22.1K_0402_1%  [R_0402]  285.05 36.92 0 top
RI49  22.1K_0402_1%  [R_0402]  285.05 36.03 0 top
RI51  1M_0402_5%  [R_0402]  277.89 36.69 0 top
RL1  0_0402_5%  [R_0402]  285.02 36.9 90 bottom
RL2  0_0402_5%  [R0402_0OHM]  286.14 39.79 90 bottom
RL19  75_0402_5%  [R_0402]  303.41 90.62 270 top
RL20  75_0402_5%  [R_0402]  300.36 90.62 270 top
RL27  100K_0402_5%  [R_0402]  279.49 53.2 270 bottom
RL30  15K_0402_1%  [R_0402]  285.91 37.81 270 bottom
RL31  2.49K_0402_1%  [R_0402]  280.82 47.48 0 bottom
RL33  1K_0402_5%  [R_0402]  287.93 37.81 180 bottom
RL39  75_0402_5%  [R_0402]  297.44 90.62 270 top
RL40  75_0402_5%  [R_0402]  294.52 90.62 270 top
RL41  100K_0402_5%  [R_0402]  277.45 48.25 180 bottom
RL42  1K_0402_5%  [R_0402]  285.63 41.6 270 top
RL43  0_0402_5%  [R0402_0OHM]  280.93 39.79 90 bottom
RM1  0_0402_5%  [R_0402]  272.17 29.84 270 top
RM2  0_0402_5%  [R_0402]  265.95 41.14 90 top
RM3  0_0402_5%  [R_0402]  265.06 41.14 90 top
RM22  0_0603_5%  [R0603_0OHM]  201.56 25.39 90 top
RM517  4.99K_0402_1%  [R_0402]  262.65 41.19 90 top
RM578  2K_0402_1%  [R_0402]  270.54 29.98 270 top
RM581  2K_0402_1%  [R_0402]  269.65 29.98 270 top
RM582  47K_0402_5%  [R_0402]  266.22 43.6 90 top
RM583  47K_0402_5%  [R_0402]  265.33 43.6 90 top
RM584  4.7K_0402_5%  [R_0402]  264.93 29.07 90 top
RM585  10K_0402_5%  [R_0402]  266.84 29.07 90 top
RM586  10K_0402_5%  [R_0402]  268.23 42.15 270 top
RM587  10K_0402_5%  [R_0402]  270.01 42.15 270 top
RM588  10K_0402_5%  [R_0402]  267.22 42.15 270 top
RM589  10K_0402_5%  [R_0402]  265.82 29.07 90 top
RM590  10K_0402_5%  [R_0402]  263.79 44.34 270 top
RM591  10K_0402_5%  [R_0402]  267.34 44.44 270 top
RM592  10K_0402_5%  [R_0402]  270.01 44.44 270 top
RM593  10K_0402_5%  [R_0402]  268.36 44.44 270 top
RM594  10K_0402_5%  [R_0402]  266.84 26.79 90 top
RM595  10K_0402_5%  [R_0402]  264.8 26.79 90 top
RM598  0_0603_5%  [R0603_0OHM]  263.53 40.38 270 bottom
RM599  0_0603_5%  [R0603_0OHM]  272.17 41.14 90 top
RM600  1K_0402_5%  [R_0402]  261.85 37.96 180 top
RN1  0_0402_5%  [R_0402]  195.15 35.09 90 bottom
RN2  0_0402_5%  [R_0402]  198.13 27.09 90 top
RN3  0_0402_5%  [R_0402]  195.16 28.69 0 top
RN4  100K_0402_5%  [R_0402]  195.16 29.58 0 top
RN5  0_0402_5%  [R0402_0OHM]  194.26 28.68 90 top
RP2  10K_0804_8P4R_5%  [RP_0804_8P4R]  169.42 17.45 90 bottom
RP3  10K_0804_8P4R_5%  [RP_0804_8P4R]  160.72 20.02 0 top
RP8  10K_0804_8P4R_5%  [RP_0804_8P4R]  154.38 36.24 180 bottom
RP15  33_0804_8P4R_5%  [RP_0804_8P4R]  181.62 15.74 90 bottom
RP22  10K_0804_8P4R_5%  [RP_0804_8P4R]  161.16 17.07 90 bottom
RP23  10K_0804_8P4R_5%  [RP_0804_8P4R]  158.24 17.07 90 bottom
RPE2  10K_0804_8P4R_5%  [RP_0804_8P4R]  233.19 34.85 90 top
RPE3  10K_0804_8P4R_5%  [RP_0804_8P4R]  229.77 32.32 270 bottom
RPE4  100K_0804_8P4R_5%  [RP_0804_8P4R]  215.5 25.45 0 top
RPE5  100K_0804_8P4R_5%  [RP_0804_8P4R]  224.43 11.48 90 top
RPE6  100K_0804_8P4R_5%  [RP_0804_8P4R]  235.27 20.32 0 bottom
RPE7  100K_0804_8P4R_5%  [RP_0804_8P4R]  239.98 22.61 180 top
RT1  7.87K_0402_1%  [R_0402]  109.31 83.94 180 top
RT3  10K_0402_5%  [R_0402]  57.08 46.47 0 bottom
RT4  10K_0402_5%  [R_0402]  55.38 47.79 90 bottom
RT5  10K_0402_5%  [R_0402]  51.32 48.2 270 bottom
RT6  0_0402_5%  [R_0402]  52.89 45.96 0 bottom
RT7  0_0402_5%  [R_0402]  53.81 49.77 180 bottom
RV27  100K_0402_5%  [R_0402]  173.64 73.55 180 bottom
RV34  10K_0402_5%  [R_0402]  150.31 74.86 270 bottom
RV37  10K_0402_5%  [R_0402]  171.46 74.67 180 top
RV39  10K_0402_5%  [R_0402]  148.07 80.44 0 bottom
RV40  0_0402_5%  [R0402_0OHM]  149.81 80.46 0 bottom
RV41  10K_0402_5%  [R_0402]  148.21 74.75 0 bottom
RV42  10K_0402_5%  [R_0402]  174.63 70.22 270 bottom
RV49  10K_0402_5%  [R_0402]  176.84 74.67 0 top
RV50  2.49K_0402_1%  [R_0402]  149.4 99.43 0 bottom
RV51  10K_0402_5%  [R_0402]  175.8 77.21 0 top
RV52  10M_0402_5%  [R_0402]  177.43 73.52 180 bottom
RV55  10K_0402_5%  [R_0402]  145.52 107.67 90 bottom
RV56  10K_0402_5%  [R_0402]  147.47 81.31 90 top
RV57  10K_0402_5%  [R_0402]  151.08 82.03 180 top
RV58  10K_0402_5%  [R_0402]  140.22 77.16 270 bottom
RV60  100K_0402_5%  [R_0402]  173.75 73.65 270 top
RV62  10K_0402_5%  [R_0402]  150.4 81.98 90 bottom
RV63  10K_0402_5%  [R_0402]  151.32 83.76 180 bottom
RV66  100K_0402_5%  [R_0402]  177.81 73.78 180 top
RV77  40.2_0402_1%  [R_0402]  174.56 97.53 0 top
RV78  40.2_0402_1%  [R_0402]  175.74 101.47 270 top
RV79  60.4_0402_1%  [R_0402]  180.9 96.61 180 top
RV95  10K_0402_5%  [R_0402]  173.49 127.45 270 top
RV96  10K_0402_5%  [R_0402]  205.7 89.53 180 top
RV98  10K_0402_5%  [R_0402]  168.67 127.09 270 top
RV99  10K_0402_5%  [R_0402]  205.57 95.46 180 top
RV107  10K_0402_5%  [R_0402]  168.7 125.35 270 top
RV108  10K_0402_5%  [R_0402]  173.49 125.54 270 top
RV110  10K_0402_5%  [R_0402]  203.82 95.49 180 top
RV111  10K_0402_5%  [R_0402]  203.92 89.48 180 top
RV116  1K_0402_1%  [R_0402]  171.71 131.56 90 top
RV117  1K_0402_1%  [R_0402]  169.8 129.45 270 top
RV120  121_0402_1%  [R_0402]  187.97 123.48 90 top
RV121  121_0402_1%  [R_0402]  154.31 123.99 90 top
RV125  549_0402_1%  [R_0402]  190.05 122.42 0 bottom
RV126  931_0402_1%  [R_0402]  190.76 120.56 90 bottom
RV127  1.33K_0402_1%  [R_0402]  188.28 124.98 90 bottom
RV131  1K_0402_1%  [R_0402]  206.26 93.51 90 top
RV132  1K_0402_1%  [R_0402]  205.17 91.18 0 top
RV135  121_0402_1%  [R_0402]  205.17 110.73 0 top
RV136  121_0402_1%  [R_0402]  201.86 75.17 0 top
RV140  549_0402_1%  [R_0402]  206.51 73.6 270 bottom
RV141  931_0402_1%  [R_0402]  201.86 73.14 0 bottom
RV142  1.33K_0402_1%  [R_0402]  203.8 74.67 0 bottom
RV146  100K_0402_5%  [R_0402]  183.52 74.03 270 top
RV147  100K_0402_5%  [R_0402]  191.39 74.36 270 top
RV148  100K_0402_5%  [R_0402]  190.51 74.41 270 top
RV149  100K_0402_5%  [R_0402]  186.69 74.36 270 top
RV150  100K_0402_5%  [R_0402]  184.53 74.36 270 top
RV152  100K_0402_5%  [R_0402]  179.94 74.93 180 top
RV153  100K_0402_5%  [R_0402]  191.02 76.32 270 top
RV154  100K_0402_5%  [R_0402]  190 76.32 270 top
RV155  100K_0402_5%  [R_0402]  186.69 76.65 270 top
RV156  100K_0402_5%  [R_0402]  184.53 76.65 270 top
RV157  100K_0402_5%  [R_0402]  187.58 74.36 270 top
RV158  100K_0402_5%  [R_0402]  189.62 74.41 270 top
RV159  100K_0402_5%  [R_0402]  185.42 74.36 270 top
RV160  100K_0402_5%  [R_0402]  187.58 76.65 270 top
RV161  100K_0402_5%  [R_0402]  188.73 75.81 90 top
RV162  100K_0402_5%  [R_0402]  185.42 76.65 270 top
RV191  1.8K_0402_5%  [R_0402]  161.38 73.52 180 bottom
RV192  1.8K_0402_5%  [R_0402]  164.35 73.6 270 bottom
RV199  0_0603_5%  [R_0603]  144.35 63.24 180 top
RV200  0_0603_5%  [R_0603]  144.35 61.97 180 top
RV208  0_0402_5%  [R0402_0OHM]  148.07 79.57 0 bottom
RV209  100K_0402_5%  [R_0402]  170.8 71.11 0 top
RV399  0_0402_5%  [R0402_0OHM]  152.3 76.32 0 top
RV512  1.8K_0402_5%  [R_0402]  170.87 81.24 0 top
RV513  1.8K_0402_5%  [R_0402]  170.88 77.46 0 top
RV514  1.8K_0402_5%  [R_0402]  165.24 73.6 270 bottom
RV515  1.8K_0402_5%  [R_0402]  168.02 73.7 270 bottom
RV526  10K_0402_5%  [R_0402]  170.7 73.52 270 bottom
RV532  10K_0402_5%  [R_0402]  147.56 76.19 0 bottom
RV534  100K_0402_5%  [R_0402]  151.43 76.44 270 top
RV535  1M_0402_5%  [R_0402]  66.89 21.83 180 top
RV536  100K_0402_5%  [R_0402]  62.8 29.96 0 top
RV537  100K_0402_5%  [R_0402]  62.8 30.98 0 top
RV538  0_0402_5%  [R0402_0OHM]  63.71 26.91 180 top
RV539  0_0402_5%  [R0402_0OHM]  55.24 37.25 0 bottom
RV540  0_0402_5%  [R0402_0OHM]  55.24 36.36 0 bottom
RV541  0_0402_5%  [R0402_0OHM]  55.24 39.03 0 bottom
RV542  0_0402_5%  [R0402_0OHM]  55.24 38.14 0 bottom
RV543  0_0402_5%  [R0402_0OHM]  55.24 40.8 0 bottom
RV544  0_0402_5%  [R0402_0OHM]  55.24 39.92 0 bottom
RV546  0_0402_5%  [R0402_0OHM]  55.24 42.71 0 bottom
RV548  0_0402_5%  [R0402_0OHM]  55.24 41.82 0 bottom
RV549  0_0402_5%  [R0402_0OHM]  55.24 34.58 0 bottom
RV551  100K_0402_5%  [R_0402]  62.8 31.87 0 top
RV552  0_0402_5%  [R0402_0OHM]  55.24 35.47 0 bottom
RV554  150_0402_5%  [R_0402]  293.81 65.27 0 top
RV557  150_0402_5%  [R_0402]  292.82 65.27 180 top
RV562  150_0402_5%  [R_0402]  296.89 75.94 180 top
RV565  150_0402_5%  [R_0402]  294.98 75.94 180 top
RV566  0_0402_5%  [R0402_0OHM]  63.71 28.95 180 top
RV567  100K_0402_5%  [R_0402]  62.77 25.95 0 top
RV570  100K_0402_5%  [R_0402]  65.97 22.72 0 top
RV571  0_0402_5%  [R_0402]  157.62 72.75 90 top
RV572  0_0402_5%  [R0402_0OHM]  145.22 73.4 0 bottom
RV573  100K_0402_5%  [R_0402]  156.73 72.75 90 top
RV574  10K_0402_5%  [R_0402]  173.75 77.51 270 top
RV575  10K_0402_5%  [R_0402]  169.81 73.65 270 bottom
RV576  10K_0402_5%  [R_0402]  168.92 73.65 270 bottom
RV577  10K_0402_5%  [R_0402]  171.99 79.77 270 top
RV578  10K_0402_5%  [R_0402]  167.14 73.7 270 bottom
RV579  10K_0402_5%  [R_0402]  171.83 73.57 270 bottom
RV580  10K_0402_5%  [R_0402]  170.1 76.56 0 top
RV581  10K_0402_5%  [R_0402]  188.48 74.29 270 top
RV582  100K_0402_5%  [R_0402]  175.42 62.86 270 top
RV583  0_0402_5%  [R0402_0OHM]  158 75.86 0 top
RV584  0_0402_5%  [R0402_0OHM]  163.55 81.5 0 top
RV585  0_0402_5%  [R0402_0OHM]  160.75 81.32 180 top
RV586  0_0402_5%  [R0402_0OHM]  163.89 80.66 270 top
RV587  0_0402_5%  [R_0402]  144.26 79.54 270 bottom
RV588  10K_0402_5%  [R_0402]  193.94 61.15 270 top
RV589  10K_0402_5%  [R_0402]  189.87 60.37 90 top
RV590  0_0402_5%  [R0402_0OHM]  155.88 82.79 180 top
RV591  1K_0402_1%  [R_0402]  153.68 72.63 180 bottom
RV592  0_0402_5%  [R0402_0OHM]  160.75 80.43 180 top
RV593  100K_0402_5%  [R_0402]  181.65 73.97 270 top
RV594  40.2_0402_1%  [R_0402]  184.29 113.91 90 bottom
RV595  40.2_0402_1%  [R_0402]  183.27 113.91 90 bottom
RV596  40.2_0402_1%  [R_0402]  155.84 114.16 90 bottom
RV597  40.2_0402_1%  [R_0402]  156.98 114.16 90 bottom
RV598  40.2_0402_1%  [R_0402]  193.94 77.59 270 bottom
RV599  40.2_0402_1%  [R_0402]  193.05 77.59 270 bottom
RV600  40.2_0402_1%  [R_0402]  192.54 104.38 90 bottom
RV601  40.2_0402_1%  [R_0402]  191.53 104.38 90 bottom
RV602  60.4_0402_1%  [R_0402]  176.92 106.42 90 top
RV603  60.4_0402_1%  [R_0402]  163.59 102.73 90 top
RV604  60.4_0402_1%  [R_0402]  181.29 85.03 0 top
RV605  60.4_0402_1%  [R_0402]  180.78 92.19 0 top
RV606  0_0402_5%  [R0402_0OHM]  199.2 58.92 90 top
RV607  1M_0402_5%  [R_0402]  201.25 53.37 180 top
RV608  0_0402_5%  [R0402_0OHM]  174.65 58.46 90 bottom
RV609  10K_0402_5%  [R_0402]  149.81 79.57 0 bottom
RV610  0_0402_5%  [R_0402]  175.42 63.69 90 top
RV611  150K_0402_5%  [R_0402]  230.07 19.22 0 bottom
RV612  100K_0402_5%  [R_0402]  231.76 16.49 0 bottom
RV613  10K_0402_5%  [R_0402]  228.29 19.84 0 bottom
RV614  0_0402_5%  [R0402_0OHM]  151.01 75.71 180 bottom
RV615  0_0402_5%  [R_0402]  148.66 77.4 90 bottom
RV616  0_0402_5%  [R0402_0OHM]  146.89 77.7 0 bottom
RV621  0_0402_5%  [R_0402]  293.76 62.91 90 top
RV622  0_0402_5%  [R_0402]  294.78 62.91 90 top
RV623  0_0402_5%  [R_0402]  291.86 62.91 90 top
RV624  0_0402_5%  [R_0402]  292.87 62.91 90 top
RV625  0_0402_5%  [R_0402]  295.92 73.57 90 top
RV626  0_0402_5%  [R_0402]  296.94 73.57 90 top
RV627  0_0402_5%  [R_0402]  294.01 73.57 90 top
RV628  0_0402_5%  [R_0402]  295.03 73.57 90 top
RW3  300_0402_5%  [R_0402]  286.73 60.06 180 bottom
RW4  300_0402_5%  [R_0402]  204.02 31.99 0 top
RZ8  10_0402_1%  [R_0402]  203.72 73.9 0 top
RZ9  10_0402_1%  [R_0402]  147.58 106.31 0 top
RZ10  10_0402_1%  [R_0402]  155.62 74.74 0 top
RZ11  100_0402_5%  [R_0402]  152.83 81.16 180 top
RZ12  100K_0402_5%  [R_0402]  206.77 73.9 270 top
RZ13  0_1206_5%  [R1206_0OHM]  212.06 11.03 180 top
RZ26  0_0603_5%  [R0603_0OHM]  64.08 33.01 180 top
RZ32  100K_0402_5%  [R_0402]  140.6 17.26 270 top
RZ33  100K_0402_5%  [R_0402]  141.49 16.37 90 top
RZ34  0_0805_5%  [R0805_0OHM]  204.06 17.64 180 bottom
RZ37  0_0603_5%  [R0603_0OHM]  228.8 48.25 0 bottom
RZ38  100K_0402_5%  [R_0402]  207.2 47.28 90 bottom
RZ40  100K_0402_5%  [R_0402]  66 35.68 180 top
RZ41  33_0402_5%  [R_0402]  241.69 38.55 270 bottom
RZ42  33_0402_5%  [R_0402]  240.67 38.55 270 bottom
RZ48  0_0603_5%  [R0603_0OHM]  133.47 97.5 0 bottom
RZ66  0_0603_5%  [R0603_0OHM]  131.72 93.93 180 top
RZ67  0_0603_5%  [R0603_0OHM]  70.63 47.4 180 top
RZ69  0_0805_5%  [R0805_0OHM]  151.64 109.15 270 bottom
RZ71  100K_0402_5%  [R_0402]  185.21 22.93 180 top
RZ73  10_0402_1%  [R_0402]  151.09 81.16 180 top
RZ96  100K_0402_5%  [R_0402]  233.18 45.76 90 bottom
RZ100  100_0402_5%  [R_0402]  154.18 81.88 270 top
RZ102  130K_0402_5%  [R_0402]  150.24 19.46 0 top
RZ103  100K_0402_5%  [R_0402]  149.96 104.28 0 top
RZ104  100K_0402_5%  [R_0402]  154.95 76.51 270 top
RZ105  100K_0402_5%  [R_0402]  157.6 82.81 180 top
RZ106  0_0402_5%  [R0402_0OHM]  152.11 108.93 90 top
RZ107  150K_0402_5%  [R_0402]  63.09 62.44 180 top
RZ108  100K_0402_5%  [R_0402]  207.08 58.64 180 top
RZ109  100K_0402_5%  [R_0402]  208.47 59.6 90 top
SW5  SKRBAAE010_4P  [SW_SKRBAAE010_4P]  292.62 65.19 270 bottom
T1  PAD~D  [TPC12]  169.66 20.01 180 bottom
T2  PAD~D  [TPC12]  152.7 33.37 180 bottom
T3  PAD~D  [TPC12]  252.14 30.29 180 bottom
T4  PAD~D  [TPC12]  154.87 40.5 180 bottom
T8  PAD~D  [TPC12]  155.5 18.93 180 bottom
T17  PAD~D  [TPC12]  170.94 19.75 180 bottom
T20  PAD~D  [TPC12]  173.09 26.6 0 top
T91  PAD~D  [TPC12]  154.59 38.29 180 bottom
T92  PAD~D  [TPC12]  169.81 27.68 0 top
T94  PAD~D  [TPC12]  155.6 37.44 180 bottom
T95  PAD~D  [TPC12]  282.57 42.17 180 bottom
T97  PAD~D  [TPC12]  179.71 80.2 0 top
T98  PAD~D  [TPC12]  151.34 82.82 180 bottom
T99  PAD~D  [TPC12]  152.36 81.99 180 bottom
T100  PAD~D  [TPC12]  152.54 85.03 180 bottom
T101  PAD~D  [TPC12]  151.14 85.04 180 bottom
T120  PAD~D  [TPC12]  154.95 29.2 180 bottom
T182  PAD~D  [TPC12]  162.92 31.09 0 top
T944  PAD~D  [TPC12]  282.8 44.02 180 bottom
T4931  PAD  [TPC12]  214.69 22.81 0 top
T4934  PAD~D  [TPC12]  171.89 27.3 0 top
TL2  MHPC_NS892407  [MHPC_NS892407_24P]  303.4 83.63 180 bottom
TV106  PAD~D  [TPC12]  163.19 74.01 180 bottom
TV107  PAD~D  [TPC12]  152.71 80.01 180 bottom
UA1  -  [G9090-180T11U_SOT23-5]  289.76 37.56 180 top
UA2  ALC1302  [ALC1302_QFN32_5X5]  261.78 21.34 270 bottom
UC1  -  [74AUP1G07GW_TSSOP5]  84.64 83.11 270 bottom
UC16  -  [74AUP1G07GW_TSSOP5]  134.89 75.67 90 top
UE1  -  [MEC1404-NU-TR_VTQFP128_14X14]  220.22 30.14 0 top
UE4  -  [SY6288D20AAC_SOT23-5]  136.86 16.43 270 top
UE6  -  [SN74LVC1G06DCKR_SC70-5]  239.13 27.31 270 bottom
UH1  SKL-H_BGA1440  [SKL-H_BGA_1440P-T]  128.21 73.73 270 bottom
UH2  SKY-H-PCH_BGA837  [SKY-S-PCH_BGA_837P-T]  178.81 43.61 0 bottom
UH7  -  [MC74VHC1G08DFT2G_SC70-5]  166.49 15.93 0 bottom
UH8  -  [W25Q128FVSIQ_SO8]  181.89 11.55 270 bottom
UH14  -  [MC74VHC1G08DFT2G_SC70-5]  190.07 27.09 180 top
UL1  RTL8111H-CG_QFN32_4X4  [RTL8111H-CG_QFN32_4X4-S]  284.61 46.74 270 bottom
UL2  -  [SY6288C20AAC_SOT23-5]  280.61 48.7 180 bottom
UM1  S IC PS8409QFN48GTR2-A1 QFN 48P REPEATER  [PS8409QFN48GTR2-A0_QFN48_6X6-S]  265.31 32.88 90 top
US1  TPS2544RTER_WQFN16_3X3  [TPS2544RTER_WQFN16_3X3-S]  282.7 36.97 180 top
US2  -  [SY6288D20AAC_SOT23-5]  291.79 41.83 0 bottom
UT1  -  [F75303M_MSOP10]  61.85 49.76 270 bottom
UV1  N17P-GT_BGA908  [N15P-GT_BGA_908P]  182.09 76.11 90 bottom
UV6  H5GC4H24MFR-T2C  [H5GQ1H24AFR-T2L_BGA_170P]  175.6 118.89 0 bottom
UV7  H5GC4H24MFR-T2C  [H5GQ1H24AFR-T2L_BGA_170P]  166.7 131.69 180 bottom
UV8  H5GC4H24MFR-T2C  [H5GQ1H24AFR-T2L_BGA_170P]  197.46 87.48 270 bottom
UV9  H5GC4H24MFR-T2C  [H5GQ1H24AFR-T2L_BGA_170P]  210.26 97.46 90 bottom
UV14  -  [MC74VHC1G08DFT2G_SC70-5]  142.31 76.3 90 bottom
UV17  -  [AP2330W-7_SC59-3]  295.16 63.05 0 bottom
UV18  TC7SZ08FU_SSOP5  [TC7SH08FU_SSOP5]  153.61 73.77 270 top
UV19  TC7SZ08FU_SSOP5  [TC7SH08FU_SSOP5]  149.74 72.38 90 top
UV21  TC7SZ08FU_SSOP5  [TC7SH08FU_SSOP5]  199.2 56.57 270 top
UV22  TC7SZ08FU_SSOP5  [TC7SH08FU_SSOP5]  174.37 64.67 90 top
UV23  TC7SZ08FU_SSOP5  [TC7SH08FU_SSOP5]  176.07 65.83 270 bottom
UZ1  -  [EM5209VF_DFN14_3X2]  215.51 11.74 90 top
UZ8  -  [SY6288C20AAC_SOT23-5]  67.51 39.54 180 top
UZ9  -  [TPS22961DNYR_WSON8]  132.72 100.19 90 bottom
UZ15  -  [TPS22961DNYR_WSON8]  132.1 99.1 180 top
UZ16  -  [APE8937GN2_DFN8_2X2]  74.21 47.28 90 top
UZ17  -  [APE8937GN2_DFN8_2X2]  147.62 109.37 90 bottom
UZ21  -  [MC74VHC1G08DFT2G_SC70-5]  187.82 24.03 180 top
UZ23  -  [MC74VHC1G08DFT2G_SC70-5]  66.7 29.26 180 top
Y1  32.768KHZ_9PF_X1A000141000200  [Y_X1A000141000200_2P]  223.38 37.07 180 top
YH1  32.768KHZ 9PF 20PPM 9H03280012  [Y_CM31532768DZFT_2P]  176.27 16.37 180 bottom
YH2  24MHZ_12PF_X3G024000DC1H  [Y_X3G024000DC1H_4P]  185.9 45.67 270 bottom
YL2  25MHZ_10PF_7V25000014  [Y_7V25000014_4P]  280.51 45.67 270 bottom
YV1  27MHZ_10PF_7V27000050  [Y_7V27000011_4P]  178.95 69.59 180 bottom

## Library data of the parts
CA1 CA8 CA10 CA11 CA13 = C_0603: room: AUDIO_DC_DC
CA2-CA4 CA7 CA9 CA12 CA14 = C_0402: room: AUDIO_DC_DC
CA15-CA17 CA20 CA21 CA24 CA26 CA28-CA33 CA36-CA47 CA52 CA54 CA55 CA57 CD91-CD95 PC114 = C_0402: room: AUDIO
CA18 CA19 CA22 CA23 CA25 CA27 CA48-CA51 CA53 CA56 PC113 = C_0603: room: AUDIO
CA34 CA35 = C_0201: room: AUDIO
CA60-CA62 CA67 CE2 CE99-CE102 CE104 CH185 CI24 CL32 CL43 CL44 CM3 CM4 CM10-CM12 CM141 CM229 CM823 CM837-CM843 CN7 CS25-CS28 CV54 CV152-CV154 CV199 CV200 CV499 CV825-CV833 CV835-CV838 CV843 CV846-CV848 CV850-CV858 CV869-CV884 CV895-CV906 CV909-CV911 CV913-CV915 CV917-CV923 CZ98 CZ102 CZ104-CZ106 CZ108 PC324 PC1523 PC1600 PC1603-PC1605 PC1608 PC1625 PC1644 PC1645 PC1655-PC1661 PC1663-PC1668 PC1676 PC1677 PC1700 PC1703-PC1705 PC1707 PC1709 PC1712 PC1713 PC1723-PC1726 PC1730-PC1732 PC1800 PC1802 PC1804 = C_0402
CA63-CA66 CE103 CM228 CN6 CV51 CV834 CV839-CV842 CV844 CV845 CV849 CV859-CV868 CV885-CV894 CV912 CV916 PC1609-PC1624 PC1626 PC1630-PC1643 PC1646-PC1653 PC1669-PC1675 PC1678 PC1701 PC1702 PC1710 PC1711 PC1714-PC1722 PC1727-PC1729 PC1733-PC1739 PC1801 PC1803 = C_0603
CC4 CC298 CH45-CH48 CH50-CH53 CH70 CH80 CH82 CH173 CH176 CH179 CH180 CH183 CH184 CH186-CH192 CH200 CH203 = C_0402: room: PCH
CC5 CH197 CZ47 CZ49 CZ57 CZ86 CZ88 = C_0402: room: CPU
CC27 = C_0402: room: RTC
CD1-CD4 CD12 CD16 CD17 CD69 CD74-CD79 CD96 CH101 = C_0402: room: DIMMA
CD5-CD10 CD13-CD15 CD70-CD73 = C_0603: room: DIMMA
CD11 = C_X: room: DIMMA
CD19-CD22 CD29-CD32 CD34 CD35 CD80-CD83 CH100 = C_0402: room: DIMMB
CD23-CD28 CD84-CD90 = C_0603: room: DIMMB
CD33 = C_APXK2R5ARA331MF451: room: DIMMB
CD36 = C_0603: room: NGFF SSD
CD37-CD46 CD51 CD53 = C_0402: room: NGFF SSD
CE1 CE4 CE5 = C_0402: room: KB
CE6 = C_0603: room: KB
CE8 CE12 CE62-CE69 CE71-CE74 CE76-CE79 CE81 CE82 CE84-CE87 CE91 CE98 = C_0402: room: EC
CE9 CE10 CE80 CT79 = C_0402: room: TOUCH PAD
CE89 = C_0603: room: EC
CH5-CH36 = C_0201: room: CPU
CH102-CH104 CH111-CH132 CH136 = C_0603: room: CPU_DECAP
CH106 CH110 CH133-CH135 CH204 = C_0402: room: CPU_DECAP
CH177 CH178 CH181 CH182 CH201 CH202 = C_0603: room: PCH
CI9 CI10 CI13 = C_0402: room: USB2
CI11 = C_0805: room: USB2
CI12 = C_0603: room: USB2
CI16 CI19 CI20 CI23 = C_0402: room: USB1
CI17 = C_0805: room: USB1
CI18 = C_0603: room: USB1
CL15 CL19-CL22 CL24 CL30 CL31 CL34-CL37 CL39 CL42 = C_0402: room: LAN
CL33 = C_1206: room: LAN
CL41 = C_0402: room: FAN
